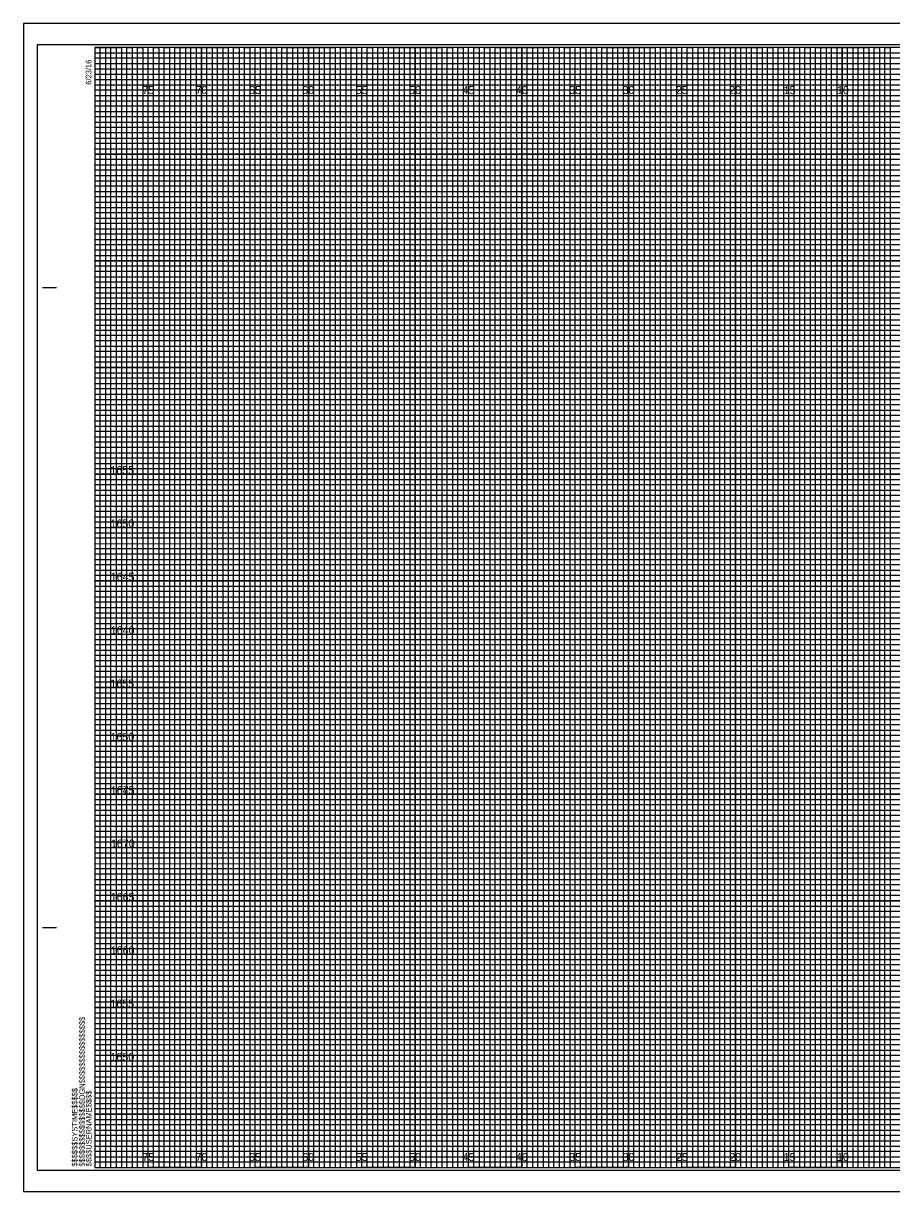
# Model space of a CAD drawing. Extents: x -7 to 162, y -2 to 107.
# Drawn here: x -6.7 to 74.6, y -2.3 to 107.3 of the extents above; entities that cross this region are included whole.
import ezdxf

# ---------------------------------------------------------------- set-up
doc = ezdxf.new("R2010")
doc.units = 0
for name, color, linetype in [('Prop Horizontal Alignment', 7, 'Continuous'), ('Scratch_Level_3', 7, 'Continuous'), ('Sheet Cross Section CELL', 7, 'Continuous'), ('Sheet Cross Section Grid Major CELL', 7, 'Continuous'), ('Sheet Cross Section Grid Middle CELL', 7, 'Continuous'), ('Sheet Cross Section Grid Minor 1 CELL', 7, 'Continuous'), ('Sheet Cross Section Grid Minor 2 CELL', 7, 'Continuous'), ('Sheet Cutting Line CELL', 7, 'Continuous'), ('Sheet DOT Grid CELL', 7, 'Continuous'), ('Sheet Plot Border Inside CELL', 7, 'Continuous'), ('Sheet Plot Border Outside CELL', 7, 'Continuous')]:
    doc.layers.add(name, color=color, linetype=linetype)

msp = doc.modelspace()

# ---------------------------------------------------------------- linework, layer by layer
at = {"layer": 'Sheet Cross Section CELL'}
for p, q in [((-4.9, 82.5), (-3.65, 82.5)), ((-4.85, 82.5), (-3.6, 82.5)), ((-4.9, 22.5), (-3.65, 22.5)), ((-4.85, 22.5), (-3.6, 22.5)), ((0, 0), (0, 0)), ((0, 0), (0, 0)), ((0, 0), (0, 0)), ((0, 0), (0, 0)), ((0, 0), (0, 0)), ((0, 0), (0, 0)), ((0, 0), (0, 0))]:
    msp.add_line(p, q, dxfattribs=at)
msp.add_lwpolyline([(160, 105), (0, 105), (0, 0), (160, 0)], close=True, dxfattribs=at)
at = {"layer": 'Sheet Cross Section Grid Major CELL'}
for p, q in [((5, 105), (0, 105)), ((5, 0), (5, 105)), ((15, 105), (10, 105)), ((10, 105), (10, 0)), ((15, 0), (15, 105)), ((25, 105), (20, 105)), ((20, 105), (20, 0)), ((25, 0), (25, 105)), ((35, 105), (30, 105)), ((30, 105), (30, 0)), ((35, 0), (35, 105)), ((45, 105), (40, 105)), ((40, 105), (40, 0)), ((45, 0), (45, 105)), ((55, 105), (50, 105)), ((50, 105), (50, 0)), ((55, 0), (55, 105)), ((65, 105), (60, 105)), ((60, 105), (60, 0)), ((65, 0), (65, 105)), ((75, 105), (70, 105)), ((70, 105), (70, 0)), ((10, 0), (5, 0)), ((20, 0), (15, 0)), ((30, 0), (25, 0)), ((40, 0), (35, 0)), ((50, 0), (45, 0)), ((60, 0), (55, 0)), ((70, 0), (65, 0))]:
    msp.add_line(p, q, dxfattribs=at)
for points in [[(0, 100), (160, 100), (160, 95), (0, 95)], [(0, 90), (160, 90), (160, 85), (0, 85)], [(0, 80), (160, 80), (160, 75), (0, 75)], [(0, 70), (160, 70), (160, 65), (0, 65)], [(0, 60), (160, 60), (160, 55), (0, 55)], [(0, 50), (160, 50), (160, 45), (0, 45)], [(0, 40), (160, 40), (160, 35), (0, 35)], [(0, 30), (160, 30), (160, 25), (0, 25)], [(0, 20), (160, 20), (160, 15), (0, 15)], [(0, 10), (160, 10), (160, 5), (0, 5)]]:
    msp.add_lwpolyline(points, dxfattribs=at)
at = {"layer": 'Sheet Cross Section Grid Middle CELL'}
for points in [[(0, 105), (2.5, 105), (2.5, 0), (7.5, 0), (7.5, 105), (12.5, 105), (12.5, 0), (17.5, 0), (17.5, 105), (22.5, 105), (22.5, 0), (27.5, 0), (27.5, 105), (32.5, 105), (32.5, 0), (37.5, 0), (37.5, 105), (42.5, 105), (42.5, 0), (47.5, 0), (47.5, 105), (52.5, 105), (52.5, 0), (57.5, 0), (57.5, 105), (62.5, 105), (62.5, 0), (67.5, 0), (67.5, 105), (72.5, 105), (72.5, 0), (77.5, 0)], [(0, 102.5), (137.5, 102.5)], [(0, 92.5), (160, 92.5), (160, 97.5), (0, 97.5)], [(0, 82.5), (160, 82.5), (160, 87.5), (0, 87.5)], [(0, 72.5), (160, 72.5), (160, 77.5), (0, 77.5)], [(0, 62.5), (160, 62.5), (160, 67.5), (0, 67.5)], [(0, 52.5), (160, 52.5), (160, 57.5), (0, 57.5)], [(0, 42.5), (160, 42.5), (160, 47.5), (0, 47.5)], [(0, 32.5), (160, 32.5), (160, 37.5), (0, 37.5)], [(0, 22.5), (160, 22.5), (160, 27.5), (0, 27.5)], [(0, 12.5), (160, 12.5), (160, 17.5), (0, 17.5)], [(0, 2.5), (160, 2.5), (160, 7.5), (0, 7.5)]]:
    msp.add_lwpolyline(points, dxfattribs=at)
at = {"layer": 'Sheet Cross Section Grid Minor 1 CELL'}
for p, q in [((0, 104.5), (130, 104.5)), ((130, 103.99), (0, 103.99)), ((0, 103.99), (0, 103.5)), ((0, 103.5), (130, 103.5)), ((130, 102.95), (0, 102.95)), ((0, 102.95), (0, 102)), ((0, 102), (160, 102))]:
    msp.add_line(p, q, dxfattribs=at)
for points in [[(0, 101.5), (135, 101.5), (160, 101.5), (160, 101), (0, 101)], [(0, 100.5), (160, 100.5), (160, 99.5), (0, 99.5)], [(0, 99), (160, 99), (160, 98.5), (0, 98.49)], [(0, 98), (160, 98), (160, 97), (0, 97)], [(0, 96.5), (160, 96.5), (160, 96), (0, 96)], [(0, 95.5), (160, 95.5), (160, 94.5), (0, 94.5)], [(0, 94), (160, 94), (160, 93.5), (0, 93.5)], [(0, 93), (160, 93), (160, 92), (0, 92)], [(0, 91.5), (160, 91.5), (160, 91), (0, 91)], [(0, 90.5), (160, 90.5), (160, 89.5), (0, 89.5)], [(0, 89), (160, 89), (160, 88.5), (0, 88.5)], [(0, 88), (160, 88), (160, 86.98), (160, 86.5), (160, 86), (0, 86)], [(0, 87), (160, 87), (160, 86.5), (0, 86.5)], [(0, 85.5), (160, 85.5), (160, 84.5), (0, 84.52)], [(0, 84.52), (160, 84.5), (160, 84), (0, 84)], [(0, 83.5), (160, 83.5), (160, 83), (0, 83)], [(0, 82), (160, 82), (160, 81.5), (0, 81.5)], [(0, 81), (160, 81), (160, 80.5), (0, 80.5)], [(-0.04, 79.45), (160, 79.45), (160, 78.94), (-0.04, 78.94)], [(0, 78.5), (160, 78.5), (160, 78), (0, 78)], [(0, 77), (160, 77), (160, 76.5), (0, 76.5)], [(0, 76), (160, 76), (160, 75.5), (0, 75.5)], [(0, 74.5), (160, 74.5), (160, 74), (0, 74)], [(0, 73.5), (160, 73.5), (160, 73), (0, 73)], [(0, 72), (160, 72), (160, 71.5), (0, 71.5)], [(0, 71), (160, 71), (160, 70.5), (0, 70.5)], [(0, 69.5), (160, 69.5), (160, 68.99), (0, 69)], [(0, 68.5), (160, 68.5), (160, 68), (0, 68)], [(0, 67), (160, 67), (160, 66.5), (0, 66.5)], [(0, 66), (160, 66), (160, 65.5), (0, 65.5)], [(0, 64.5), (160, 64.5), (160, 64), (0, 64)], [(0, 63.5), (160, 63.5), (160, 63), (0, 63)], [(0, 62), (160, 62), (160, 61.5), (0, 61.5)], [(0, 61), (160, 61), (160, 60.5), (0, 60.5)], [(0, 59.5), (160, 59.5), (160, 59), (0, 59)], [(0, 58.5), (160.03, 58.45), (160, 58), (0, 58)], [(0, 57), (160, 57), (160, 56.5), (0, 56.5)], [(0, 56), (160, 56), (160, 55.5), (0, 55.5)], [(0, 54.5), (160, 54.5), (160, 54), (0, 54)], [(0, 53.5), (160, 53.5), (160, 53), (0, 53)], [(0, 52), (160, 52), (160, 51.5), (0, 51.5)], [(0, 51), (160, 51), (160, 50.5), (0, 50.5)], [(0, 49.5), (160, 49.5), (160, 49), (0, 49)], [(0, 48.5), (160, 48.5), (160, 48), (0, 48)], [(0, 47), (160, 47), (160, 46.5), (0, 46.5)], [(0, 46), (160, 46), (160, 45.5), (0, 45.5)], [(0, 44.5), (160, 44.5), (160, 44), (0, 44)], [(0, 43.5), (160, 43.5), (160, 43), (0, 43)], [(0, 42), (160, 42), (160, 41.5), (0, 41.5)], [(0, 41), (160, 41), (160, 40.5), (0, 40.5)], [(0, 39.5), (160, 39.5), (160, 38.99), (0, 39)], [(0, 38.5), (160, 38.5), (160, 38), (0, 38)], [(0, 37), (160, 37), (160, 36.5), (0, 36.5)], [(0, 36), (160, 36), (160, 35.5), (0, 35.5)], [(0, 34.5), (160, 34.5), (160, 34), (0, 34)], [(0, 33.5), (160, 33.5), (160, 33), (0, 33)], [(0, 32), (160, 32), (160, 31.5), (0, 31.5)], [(0, 31), (160, 31), (160, 30.5), (0, 30.5)], [(0, 29.5), (160, 29.5), (160, 29), (0, 29)], [(0, 28.5), (160.03, 28.46), (160, 28), (0, 28)], [(0, 27), (160, 27), (160, 26.5), (0, 26.5)], [(0, 26), (160, 26), (160, 25.5), (0, 25.5)], [(0, 24.5), (160, 24.5), (160, 24), (0, 24)], [(0, 23.5), (160, 23.5), (160, 23), (0, 23)], [(0, 22), (160, 22), (160, 21.5), (0, 21.5)], [(0, 21), (160, 21), (160, 20.5), (0, 20.5)], [(0, 19.5), (160, 19.5), (160, 19), (0, 19)], [(0, 18.5), (160, 18.5), (160, 18), (0, 18)], [(0, 17), (160, 17), (160, 16.5), (0, 16.5)], [(0, 16), (160, 16), (160, 15.5), (0, 15.5)], [(0, 14.5), (160, 14.5), (160, 14), (0, 14)], [(0, 13.5), (160, 13.5), (160, 13), (0, 13)], [(0, 12), (160, 12), (160, 11.5), (0, 11.5)], [(0, 11), (160, 11), (160, 10.5), (0, 10.5)], [(0, 9.5), (160, 9.5), (160, 9), (0, 9)], [(0, 8.5), (160, 8.5), (160, 8), (0, 8)], [(0, 7), (160, 7), (160, 6.5), (0, 6.5)], [(0, 6), (160, 6), (160, 5.5), (0, 5.5)], [(0, 4.5), (160, 4.5), (160, 4), (0, 4)], [(0, 3.5), (160, 3.5), (160, 3), (0, 3)], [(0, 2), (160, 2), (160, 1.5), (0, 1.5)], [(0, 1), (160, 1), (160, 0.5), (0, 0.5)]]:
    msp.add_lwpolyline(points, dxfattribs=at)
at = {"layer": 'Sheet Cross Section Grid Minor 2 CELL'}
for points in [[(0, 0), (0.5, 0), (0.5, 105), (1, 105), (1, 0)], [(1, 0), (1.5, 0), (1.5, 105), (2, 105), (2, 0)], [(2.5, 0), (3, 0), (3, 105), (3.5, 105), (3.5, 0)], [(3.5, 0), (4, 0), (4, 105), (4.5, 105), (4.5, 0)], [(5, 0), (5.5, 0), (5.5, 105), (6, 105), (6, 0)], [(6, 0), (6.5, 0), (6.5, 105), (7, 105), (7, 0)], [(7.5, 0), (8, 0), (8, 105), (8.5, 105), (8.5, 0)], [(8.5, 0), (9, 0), (9, 105), (9.5, 105), (9.5, 0)], [(10, 0), (10.5, 0), (10.5, 105), (11, 105), (11, 0)], [(11, 0), (11.5, 0), (11.5, 105), (12, 105), (12, 0)], [(12.5, 0), (13, 0), (13, 105), (13.5, 105), (13.5, 0)], [(13.5, 0), (14, 0), (14, 105), (14.5, 105), (14.5, 0)], [(15, 0), (15.5, 0), (15.5, 105), (16, 105), (16, 0)], [(16, 0), (16.5, 0), (16.5, 105), (17, 105), (17, 0)], [(17.5, 0), (18, 0), (18, 105), (18.5, 105), (18.5, 0)], [(18.5, 0), (19, 0), (19, 105), (19.5, 105), (19.5, 0)], [(20, 0), (20.5, 0), (20.5, 105), (21, 105), (21, 0)], [(21, 0), (21.5, 0), (21.5, 105), (22, 105), (22, 0)], [(22.5, 0), (23, 0), (23, 105), (23.5, 105), (23.5, 0)], [(23.5, 0), (24, 0), (24, 105), (24.5, 105), (24.5, 0)], [(25, 0), (25.5, 0), (25.5, 105), (26, 105), (26, 0)], [(26, 0), (26.5, 0), (26.5, 105), (27, 105), (27, 0)], [(27.5, 0), (28, 0), (28, 105), (28.5, 105), (28.5, 0)], [(28.5, 0), (29, 0), (29, 105), (29.5, 105), (29.5, 0)], [(30, 0), (30.5, 0), (30.5, 105), (31, 105), (31, 0)], [(31, 0), (31.5, 0), (31.5, 105), (32, 105), (32, 0)], [(32.5, 0), (33, 0), (33, 105), (33.5, 105), (33.5, 0)], [(33.5, 0), (34, 0), (34, 105), (34.5, 105), (34.5, 0)], [(35, 0), (35.5, 0), (35.5, 105), (36, 105), (36, 0)], [(36, 0), (36.5, 0), (36.5, 105), (37, 105), (37, 0)], [(37.5, 0), (38, 0), (38, 105), (38.5, 105), (38.5, 0)], [(38.5, 0), (39, 0), (39, 105), (39.5, 105), (39.5, 0)], [(40, 0), (40.5, 0), (40.5, 105), (41, 105), (41, 0)], [(41, 0), (41.5, 0), (41.5, 105), (42, 105), (42, 0)], [(42.5, 0), (43, 0), (43, 105), (43.5, 105), (43.5, 0)], [(43.5, 0), (44, 0), (44, 105), (44.5, 105), (44.5, 0)], [(45, 0), (45.5, 0), (45.5, 105), (46, 105), (46, 0)], [(46, 0), (46.5, 0), (46.5, 105), (47, 105), (47, 0)], [(47.5, 0), (48, 0), (48, 105), (48.5, 105), (48.5, 0)], [(48.5, 0), (49, 0), (49, 105), (49.5, 105), (49.5, 0)], [(50, 0), (50.5, 0), (50.5, 105), (51, 105), (51, 0)], [(51, 0), (51.5, 0), (51.5, 105), (52, 105), (52, 0)], [(52.5, 0), (53, 0), (53, 105), (53.5, 105), (53.5, 0)], [(53.5, 0), (54, 0), (54, 105), (54.5, 105), (54.5, 0)], [(55, 0), (55.5, 0), (55.5, 105), (56, 105), (56, 0)], [(56, 0), (56.5, 0), (56.5, 105), (57, 105), (57, 0)], [(57.5, 0), (58, 0), (58, 105), (58.5, 105), (58.5, 0)], [(58.5, 0), (59, 0), (59, 105), (59.5, 105), (59.5, 0)], [(60, 0), (60.5, 0), (60.5, 105), (61, 105), (61, 0)], [(61, 0), (61.5, 0), (61.5, 105), (62, 105), (62, 0)], [(62.5, 0), (63, 0), (63, 105), (63.5, 105), (63.5, 0)], [(63.5, 0), (64, 0), (64, 105), (64.5, 105), (64.5, 0)], [(65, 0), (65.5, 0), (65.5, 105), (66, 105), (66, 0)], [(66, 0), (66.5, 0), (66.5, 105), (67, 105), (67, 0)], [(67.5, 0), (68, 0), (68, 105), (68.5, 105), (68.5, 0)], [(68.5, 0), (69, 0), (69, 105), (69.5, 105), (69.5, 0)], [(70, 0), (70.5, 0), (70.5, 105), (71, 105), (71, 0)], [(71, 0), (71.5, 0), (71.5, 105), (72, 105), (72, 0)], [(72.5, 0), (73, 0), (73, 105), (73.5, 105), (73.5, 0)], [(73.5, 0), (74, 0), (74, 105), (74.5, 105), (74.5, 0)]]:
    msp.add_lwpolyline(points, dxfattribs=at)
at = {"layer": 'Sheet Cutting Line CELL'}
for p, q in [((161.65, 107.25), (-6.7, 107.25)), ((-6.7, 107.25), (-6.7, -2.25)), ((-6.7, -2.25), (161.65, -2.25))]:
    msp.add_line(p, q, dxfattribs=at)
at = {"layer": 'Sheet DOT Grid CELL'}
for p, q in [((5, 0), (5, 105)), ((10, 0), (10, 105)), ((15, 0), (15, 105)), ((20, 0), (20, 105)), ((25, 0), (25, 105)), ((30, 0), (30, 105)), ((35, 0), (35, 105)), ((40, 0), (40, 105)), ((45, 0), (45, 105)), ((50, 0), (50, 105)), ((55, 0), (55, 105)), ((60, 0), (60, 105)), ((65, 0), (65, 105)), ((70, 0), (70, 105)), ((0, 100), (160, 100)), ((0, 95), (160, 95)), ((0, 90), (160, 90)), ((0, 85), (160, 85)), ((0, 80), (160, 80)), ((0, 75), (160, 75)), ((0, 70), (160, 70)), ((0, 65), (160, 65)), ((0, 60), (160, 60)), ((0, 55), (160, 55)), ((0, 50), (160, 50)), ((0, 45), (160, 45)), ((0, 40), (160, 40)), ((0, 35), (160, 35)), ((0, 30), (160, 30)), ((0, 25), (160, 25)), ((0, 20), (160, 20)), ((0, 15), (160, 15)), ((0, 10), (160, 10)), ((0, 5), (160, 5))]:
    msp.add_line(p, q, dxfattribs=at)
at = {"layer": 'Sheet Plot Border Inside CELL'}
msp.add_lwpolyline([(-5.4, -0.25), (161.2, -0.25), (161.2, 105.25), (-5.4, 105.25)], close=True, dxfattribs=at)
at = {"layer": 'Sheet Plot Border Outside CELL'}
msp.add_lwpolyline([(-6.7, -2.25), (161.65, -2.25), (161.65, 107.25), (-6.7, 107.25)], close=True, dxfattribs=at)

# ---------------------------------------------------------------- texts
at = {"layer": 'Prop Horizontal Alignment'}
for s, p in [('1655', (1.45, 65)), ('1650', (1.46, 60)), ('1645', (1.48, 55)), ('1640', (1.48, 50)), ('1655', (1.45, 45)), ('1650', (1.46, 40)), ('1645', (1.48, 35)), ('1675', (1.49, 35)), ('1670', (1.5, 30)), ('1665', (1.48, 25)), ('1660', (1.48, 20)), ('1655', (1.45, 15)), ('1650', (1.46, 10))]:
    msp.add_text(s, height=0.75, dxfattribs=at).set_placement(p)
at = {"layer": 'Scratch_Level_3'}
for s, p in [('75', (4.44, 100.62)), ('70', (9.43, 100.62)), ('65', (14.44, 100.62)), ('60', (19.43, 100.62)), ('55', (24.44, 100.62)), ('50', (29.43, 100.62)), ('45', (34.44, 100.62)), ('40', (39.43, 100.62)), ('35', (44.44, 100.62)), ('30', (49.43, 100.62)), ('25', (54.44, 100.62)), ('20', (59.43, 100.62)), ('15', (64.53, 100.62)), ('10', (69.52, 100.62)), ('75', (4.44, 0.62)), ('70', (9.43, 0.62)), ('65', (14.44, 0.62)), ('60', (19.43, 0.62)), ('55', (24.44, 0.62)), ('50', (29.43, 0.62)), ('45', (34.44, 0.62)), ('40', (39.43, 0.62)), ('35', (44.44, 0.62)), ('30', (49.43, 0.62)), ('25', (54.44, 0.62)), ('20', (59.43, 0.62)), ('15', (64.53, 0.62)), ('10', (69.52, 0.62))]:
    msp.add_text(s, height=0.75, dxfattribs=at).set_placement(p)
at = {"layer": 'Sheet Cross Section CELL'}
for s, p in [('6/23/16', (-0.33, 101.5)), ('$$$$$$$$$$$$$$$$DGN$$$$$$$$$$$$$$$$', (-0.94, 0.09)), ('$$$$$$SYSTIME$$$$$', (-1.63, 0.09)), ('$$$$USERNAME$$$$', (-0.31, 0.12))]:
    msp.add_text(s, height=0.525, rotation=90, dxfattribs=at).set_placement(p)

doc.saveas('drawing.dxf')
